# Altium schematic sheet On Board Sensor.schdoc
size 269 x 204 mm
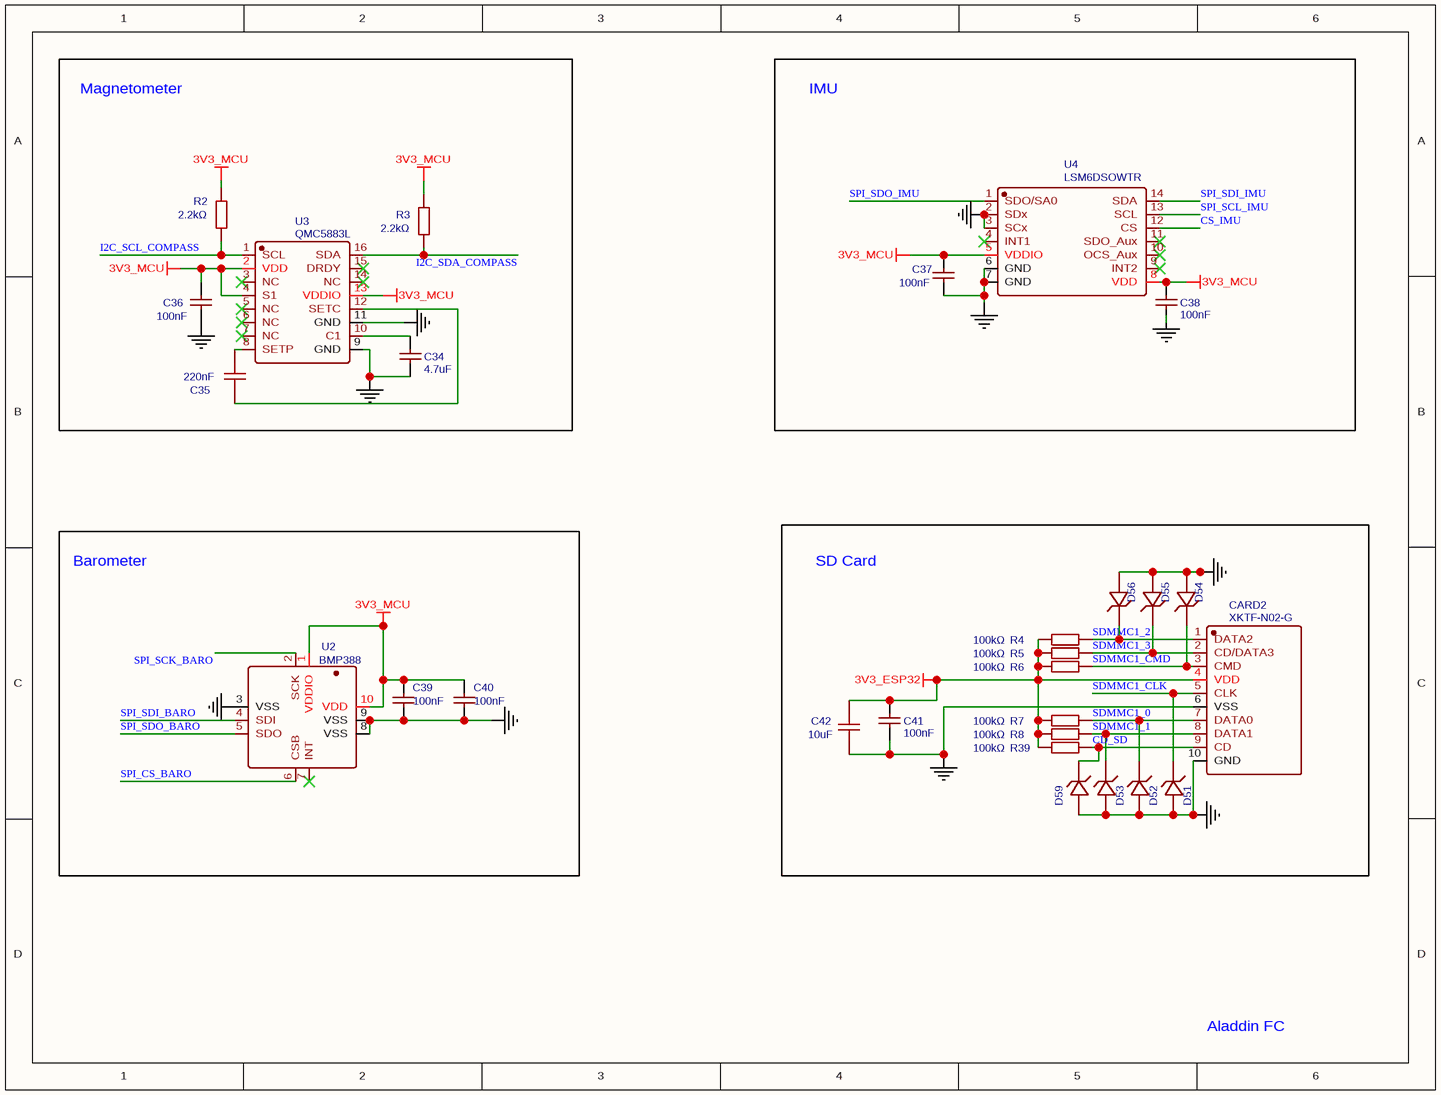
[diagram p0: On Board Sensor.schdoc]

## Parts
C34  4.7uF  [C0805]
C35  220nF  [C0805]
C36  100nF  [C0805]
C37  100nF  [C0805]
C38  100nF  [C0805]
C39  100nF  [C0805]
C40  100nF  [C0805]
C41  100nF  [C0805]
C42  10uF  [C0805]
CARD2  XKTF-N02-G  [TF-SMD_XKTF-N02-G]
D51  ESD9X5V-2/TR  [FBP-02C_L1.0-W0.6-RD]  (value not drawn)
D52  ESD9X5V-2/TR  [FBP-02C_L1.0-W0.6-RD]  (value not drawn)
D53  ESD9X5V-2/TR  [FBP-02C_L1.0-W0.6-RD]  (value not drawn)
D54  ESD9X5V-2/TR  [FBP-02C_L1.0-W0.6-RD]  (value not drawn)
D55  ESD9X5V-2/TR  [FBP-02C_L1.0-W0.6-RD]  (value not drawn)
D56  ESD9X5V-2/TR  [FBP-02C_L1.0-W0.6-RD]  (value not drawn)
D59  ESD9X5V-2/TR  [FBP-02C_L1.0-W0.6-RD]  (value not drawn)
R2  2.2kΩ  [R0805]
R3  2.2kΩ  [R0805]
R4  100kΩ  [R0805]
R5  100kΩ  [R0805]
R6  100kΩ  [R0805]
R7  100kΩ  [R0805]
R8  100kΩ  [R0805]
R39  100kΩ  [R0805]
U2  BMP388  [SENSORM-SMD_BMP388]
U3  QMC5883L  [LGA-16_L3.0-W3.0-P0.50-BL_SQ]
U4  LSM6DSOWTR  [LGA-14L_L3.0-W2.5-P0.50-TL]

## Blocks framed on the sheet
Magnetometer: C34-C36 R2 R3 U3
IMU: C37 C38 U4
Barometer: C39 C40 U2
SD Card: C41 C42 CARD2 D51-D56 D59 R4-R8 R39

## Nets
3V3_ESP32: C41.2 C42.2 CARD2.4(VDD) R4.1 R5.1 R6.1 R7.1 R8.1 R39.1
3V3_MCU: C36.2 C37.2 C38.2 C39.1 C40.1 R2.2 R3.2 U2.1(VDDIO) U2.10(VDD) U3.2(VDD) U3.4(S1) U3.13(VDDIO) U4.5(VDDIO) U4.8(VDD)
GND: C34.1 C36.1 C37.1 C38.1 C39.2 C40.2 C41.1 C42.1 CARD2.6(VSS) CARD2.10(GND) D51.2 D52.2 D53.2 D54.2 D55.2 D56.2 D59.2 U2.3(VSS) U2.8(VSS) U2.9(VSS) U3.9(GND) U3.11(GND) U4.2(SDx) U4.3(SCx) U4.6(GND) U4.7(GND)
CD_SD: CARD2.9(CD) D59.1 R39.2
CS_IMU: U4.12(CS)
I2C_SCL_COMPASS: R2.1 U3.1(SCL)
I2C_SDA_COMPASS: R3.1 U3.16(SDA)
SDMMC1_0: CARD2.7(DATA0) D52.1 R7.2
SDMMC1_1: CARD2.8(DATA1) D53.1 R8.2
SDMMC1_2: CARD2.1(DATA2) D56.1 R4.2
SDMMC1_3: CARD2.2(CD/DATA3) D55.1 R5.2
SDMMC1_CLK: CARD2.5(CLK) D51.1
SDMMC1_CMD: CARD2.3(CMD) D54.1 R6.2
SPI_CS_BARO: U2.6(CSB)
SPI_SCK_BARO: U2.2(SCK)
SPI_SCL_IMU: U4.13(SCL)
SPI_SDI_BARO: U2.4(SDI)
SPI_SDI_IMU: U4.14(SDA)
SPI_SDO_BARO: U2.5(SDO)
SPI_SDO_IMU: U4.1(SDO/SA0)
NetC34_2: C34.2 U3.10(C1)
NetC35_1: C35.1 U3.12(SETC)
NetC35_2: C35.2 U3.8(SETP)

Not connected (* = marked no-connect by the designer): U2 7(INT)*; U3 3(NC)* 5(NC)* 6(NC)* 7(NC)* 14(NC)* 15(DRDY)*; U4 4(INT1)* 9(INT2)* 10(OCS_Aux)* 11(SDO_Aux)*

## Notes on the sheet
- Aladdin FC

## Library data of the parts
C34 = 4.7uF: BOM_Manufacturer: SAMSUNG; BOM_Manufacturer Part: CL21B475KAFNNNE; nameAlias: Capacitance
C35 = 220nF: BOM_Manufacturer: YAGEO; BOM_Manufacturer Part: CC0805ZRY5V8BB224; nameAlias: Capacitance; Contributor: LCSC
C36-C41 = 100nF: BOM_Manufacturer Part: CL21B104KBCNNNC; BOM_Manufacturer: SAMSUNG; nameAlias: Capacitance
C42 = 10uF: BOM_Manufacturer: Taiyo Yuden; BOM_Manufacturer Part: TMK212BBJ106KGHT; nameAlias: Capacitance; Contributor: LCSC
CARD2 = XKTF-N02-G: BOM_Manufacturer: XKB Connectivity; Contributor: LCSC
D51-D56 D59 = ESD9X5V-2/TR: BOM_Manufacturer: Will Semicon; Contributor: LCSC
R2 R3 = 2.2kΩ: BOM_Manufacturer: Viking Tech; BOM_Manufacturer Part: AR05BTB2201; Resistance (Ohms): 2.2K; nameAlias: Resistance; Contributor: LCSC
R4-R8 R39 = 100kΩ: BOM_Manufacturer: Viking Tech; BOM_Manufacturer Part: ARG05BTC1003; Resistance (Ohms): 100K; nameAlias: Resistance; Contributor: LCSC
U2 = BMP388: BOM_Manufacturer: null; Contributor: LCSC
U3 = QMC5883L: BOM_Manufacturer: QST(上海矽睿); Contributor: LCSC
U4 = LSM6DSOWTR: BOM_Manufacturer: ST(意法半导体); Contributor: lcsc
